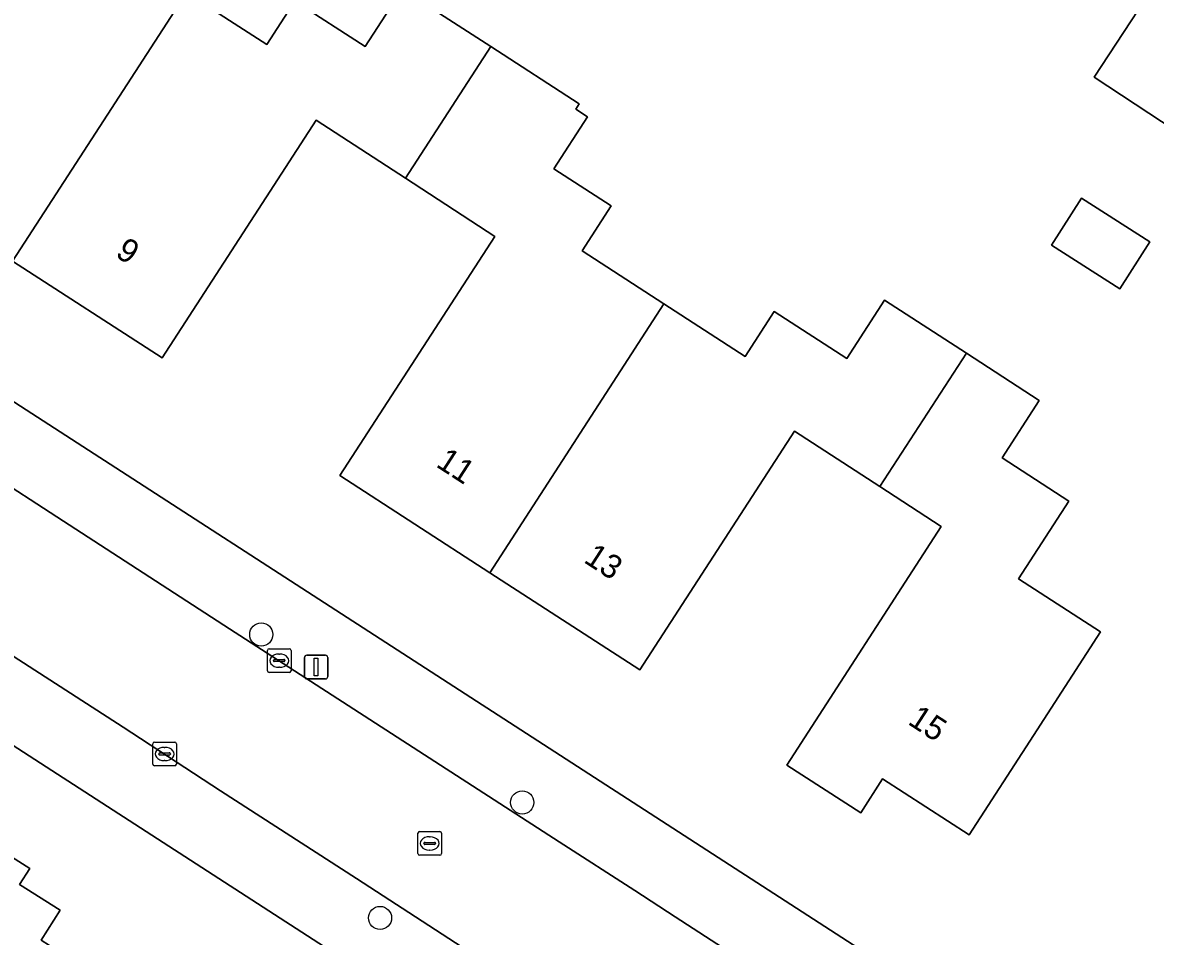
# Model space of a CAD drawing. Extents: x 161139 to 161601, y 381708 to 382245.
# Drawn here: x 161394.2 to 161442.02, y 382009.56 to 382048.13 of the extents above; entities that cross this region are included whole.
import ezdxf

# ---------------------------------------------------------------- set-up
doc = ezdxf.new("R2010")
doc.units = 0
for name, color, linetype in [('IMGEO_Boom', 7, 'Continuous'), ('IMGEO_Erf', 7, 'Continuous'), ('IMGEO_Kolk', 7, 'Continuous'), ('IMGEO_Lichtmast', 7, 'Continuous'), ('IMGEO_Pand', 7, 'Continuous'), ('IMGEO_Pand_nummerreeks', 7, 'Continuous'), ('IMGEO_Rijbaan_lokaal_open', 7, 'Continuous'), ('IMGEO_Rioolput', 7, 'Continuous'), ('IMGEO_Voetpad_open', 7, 'Continuous')]:
    doc.layers.add(name, color=color, linetype=linetype)

msp = doc.modelspace()

# ---------------------------------------------------------------- linework, layer by layer
at = {"layer": 'IMGEO_Boom'}
for centre in [(161404.273, 382022.3), (161415.291, 382015.211), (161409.287, 382010.334)]:
    msp.add_circle(centre, 0.489, dxfattribs=at)
at = {"layer": 'IMGEO_Erf'}
for points in [[(161320.525, 382089.631), (161313.623, 382083.997), (161443.483, 382000), (161462.38, 381987.777), (161470.3, 382000), (161498.24, 382043.117), (161359.011, 382133.266)], [(161421.048, 382000), (161306.066, 382074.349)], [(161401.11, 382049.396), (161404.506, 382047.197), (161405.696, 382049.035), (161408.654, 382047.119), (161410.222, 382049.541), (161413.97, 382047.113), (161417.695, 382044.701), (161417.547, 382044.473), (161418.047, 382044.149), (161416.628, 382041.957), (161419.046, 382040.391), (161417.818, 382038.494), (161421.274, 382036.256), (161424.699, 382034.038), (161425.925, 382035.931), (161428.991, 382033.945), (161430.587, 382036.409), (161434.04, 382034.173), (161437.118, 382032.18), (161435.549, 382029.755), (161438.371, 382027.928), (161436.248, 382024.648), (161439.71, 382022.407), (161436.878, 382018.034), (161434.16, 382013.837), (161430.507, 382016.202), (161429.579, 382014.769), (161426.46, 382016.788), (161432.983, 382026.86), (161430.388, 382028.546), (161426.785, 382030.887), (161420.257, 382020.807), (161413.923, 382024.909), (161407.591, 382029.009), (161414.13, 382039.106), (161410.358, 382041.557), (161406.584, 382044.008), (161400.087, 382033.974), (161393.772, 382038.063)], [(161391.396, 382014.399), (161394.499, 382012.428), (161394.066, 382011.748), (161395.777, 382010.661), (161394.975, 382009.398), (161396.031, 382008.728), (161393.351, 382004.508)]]:
    msp.add_lwpolyline(points, dxfattribs=at)
for points in [[(161442.858, 382051.048), (161448.016, 382047.664), (161444.589, 382042.441), (161439.431, 382045.825)], [(161440.525, 382036.894), (161437.64, 382038.735), (161438.905, 382040.719), (161441.791, 382038.879)]]:
    msp.add_lwpolyline(points, close=True, dxfattribs=at)
at = {"layer": 'IMGEO_Kolk'}
for p, q in [((161404.532, 382020.77), (161404.532, 382021.622)), ((161404.607, 382021.696), (161405.459, 382021.696)), ((161405.533, 382021.622), (161405.533, 382020.77)), ((161404.791, 382021.19), (161404.791, 382021.202)), ((161405.229, 382021.153), (161404.831, 382021.153)), ((161404.834, 382021.239), (161405.232, 382021.239)), ((161405.02, 382021.476), (161405.045, 382021.476)), ((161405.275, 382021.202), (161405.275, 382021.19)), ((161405.459, 382020.696), (161404.607, 382020.696)), ((161405.043, 382020.916), (161405.018, 382020.916)), ((161399.692, 382016.83), (161399.692, 382017.682)), ((161399.767, 382017.756), (161400.619, 382017.756)), ((161400.693, 382017.682), (161400.693, 382016.83)), ((161399.951, 382017.25), (161399.951, 382017.262)), ((161400.389, 382017.213), (161399.991, 382017.213)), ((161399.994, 382017.299), (161400.392, 382017.299)), ((161400.18, 382017.536), (161400.205, 382017.536)), ((161400.435, 382017.262), (161400.435, 382017.25)), ((161400.619, 382016.756), (161399.767, 382016.756)), ((161400.203, 382016.976), (161400.178, 382016.976))]:
    msp.add_line(p, q, dxfattribs=at)
for points in [[(161404.532, 382020.77), (161404.532, 382021.622)], [(161404.607, 382021.696), (161405.459, 382021.696)], [(161405.533, 382021.622), (161405.533, 382020.77)], [(161405.459, 382020.696), (161404.607, 382020.696)], [(161399.692, 382016.83), (161399.692, 382017.682)], [(161399.767, 382017.756), (161400.619, 382017.756)], [(161400.693, 382017.682), (161400.693, 382016.83)], [(161400.619, 382016.756), (161399.767, 382016.756)]]:
    msp.add_lwpolyline(points, dxfattribs=at)
for centre, radius, start, end in [((161404.609, 382021.62), 0.0765, 91.552, 178.448), ((161404.609, 382021.62), 0.0765, 91.552, 178.448), ((161405.457, 382021.62), 0.0765, 1.552, 88.448), ((161405.457, 382021.62), 0.0765, 1.552, 88.448), ((161404.831, 382021.199), 0.0403, 85.8775, 175.7526), ((161404.828, 382021.189), 0.0366, 178.938, 274.7102), ((161405.232, 382021.196), 0.043, 264.8664, 352.4533), ((161405.236, 382021.201), 0.0386, 1.7309, 96.639), ((161404.609, 382020.772), 0.0765, 181.552, 268.448), ((161404.609, 382020.772), 0.0765, 181.552, 268.448), ((161405.457, 382020.772), 0.0765, 271.552, 358.448), ((161405.457, 382020.772), 0.0765, 271.552, 358.448), ((161399.769, 382017.68), 0.0765, 91.552, 178.448), ((161399.769, 382017.68), 0.0765, 91.552, 178.448), ((161400.617, 382017.68), 0.0765, 1.552, 88.448), ((161400.617, 382017.68), 0.0765, 1.552, 88.448), ((161399.991, 382017.259), 0.0403, 85.8775, 175.7526), ((161399.988, 382017.249), 0.0366, 178.938, 274.7102), ((161400.392, 382017.256), 0.043, 264.8664, 352.4533), ((161400.396, 382017.261), 0.0386, 1.7309, 96.639), ((161399.769, 382016.832), 0.0765, 181.552, 268.448), ((161399.769, 382016.832), 0.0765, 181.552, 268.448), ((161400.617, 382016.832), 0.0765, 271.552, 358.448), ((161400.617, 382016.832), 0.0765, 271.552, 358.448)]:
    msp.add_arc(centre, radius, start, end, dxfattribs=at)
for centre, major_axis, ratio, start_param, end_param in [((161405.019, 382021.196), (-0.387, 0.002), 0.722429, 4.712389, 7.853982), ((161405.044, 382021.196), (-0.39, 0.002), 0.717154, 1.570796, 4.712389), ((161400.179, 382017.256), (-0.387, 0.002), 0.722429, 4.712389, 7.853982), ((161400.204, 382017.256), (-0.39, 0.002), 0.717154, 1.570796, 4.712389)]:
    msp.add_ellipse(centre, major_axis=major_axis, ratio=ratio, start_param=start_param, end_param=end_param, dxfattribs=at)
at = {"layer": 'IMGEO_Lichtmast'}
for p, q in [((161406.093, 382020.525), (161406.093, 382021.325)), ((161406.093, 382021.325), (161406.093, 382020.525)), ((161406.193, 382021.425), (161406.983, 382021.425)), ((161406.983, 382021.425), (161406.193, 382021.425)), ((161407.083, 382021.325), (161407.083, 382020.525)), ((161407.083, 382020.525), (161407.083, 382021.325)), ((161406.983, 382020.425), (161406.193, 382020.425)), ((161406.193, 382020.425), (161406.983, 382020.425))]:
    msp.add_line(p, q, dxfattribs=at)
msp.add_lwpolyline([(161406.513, 382021.3), (161406.663, 382021.3), (161406.663, 382020.55), (161406.513, 382020.55), (161406.513, 382021.3)], dxfattribs=at)
for centre, start, end in [((161406.193, 382021.325), 90, 180), ((161406.193, 382021.325), 90, 180), ((161406.983, 382021.325), 0, 90), ((161406.983, 382021.325), 360, 90), ((161406.193, 382020.525), 180, 270), ((161406.193, 382020.525), 180, 270), ((161406.983, 382020.525), 270, 0), ((161406.983, 382020.525), 270, 0)]:
    msp.add_arc(centre, 0.1, start, end, dxfattribs=at)
at = {"layer": 'IMGEO_Pand'}
for points in [[(161393.772, 382038.063), (161401.11, 382049.396), (161397.803, 382051.538), (161399.046, 382053.458), (161396.573, 382055.059), (161397.487, 382056.47), (161396.939, 382056.824), (161397.496, 382057.684), (161393.835, 382060.054), (161390.289, 382054.594), (161393.97, 382052.203), (161387.46, 382042.15)], [(161448.016, 382047.664), (161442.858, 382051.048), (161439.431, 382045.825), (161444.589, 382042.441)], [(161401.11, 382049.396), (161393.772, 382038.063), (161400.087, 382033.974), (161406.584, 382044.008), (161410.358, 382041.557), (161413.97, 382047.113), (161410.222, 382049.541), (161408.654, 382047.119), (161405.696, 382049.035), (161404.506, 382047.197)], [(161413.97, 382047.113), (161410.358, 382041.557), (161414.13, 382039.106), (161407.591, 382029.009), (161413.923, 382024.909), (161421.274, 382036.256), (161417.818, 382038.494), (161419.046, 382040.391), (161416.628, 382041.957), (161418.047, 382044.149), (161417.547, 382044.473), (161417.695, 382044.701)], [(161440.525, 382036.894), (161441.791, 382038.879), (161438.905, 382040.719), (161437.64, 382038.735)], [(161413.923, 382024.909), (161420.257, 382020.807), (161426.785, 382030.887), (161430.388, 382028.546), (161434.04, 382034.173), (161430.587, 382036.409), (161428.991, 382033.945), (161425.925, 382035.931), (161424.699, 382034.038), (161421.274, 382036.256)], [(161430.388, 382028.546), (161432.983, 382026.86), (161426.46, 382016.788), (161429.579, 382014.769), (161430.507, 382016.202), (161434.16, 382013.837), (161436.878, 382018.034), (161439.71, 382022.407), (161436.248, 382024.648), (161438.371, 382027.928), (161435.549, 382029.755), (161437.118, 382032.18), (161434.04, 382034.173)], [(161396.031, 382008.728), (161394.975, 382009.398), (161395.777, 382010.661), (161394.066, 382011.748), (161394.499, 382012.428), (161391.396, 382014.399), (161391.004, 382013.782), (161390.576, 382014.054), (161384.011, 382003.694), (161387.531, 382001.458), (161384.298, 381996.37), (161390.905, 381992.091), (161391.465, 381992.964), (161394.166, 381997.171), (161390.296, 381999.701), (161391.78, 382002.036), (161393.351, 382004.508)]]:
    msp.add_lwpolyline(points, close=True, dxfattribs=at)
at = {"layer": 'IMGEO_Rijbaan_lokaal_open'}
for points in [[(161470.897, 381978.482), (161460.91, 381984.988), (161458.647, 381986.439), (161425.551, 382007.922), (161421.741, 382010.379), (161420.042, 382011.494), (161416.852, 382013.552), (161402.927, 382022.535), (161395.928, 382027.083), (161382.572, 382035.748), (161375.585, 382040.285)], [(161388.068, 382025.069), (161398.439, 382018.395), (161402.555, 382015.697), (161408.287, 382012.005), (161423.318, 382002.239), (161430.314, 381997.713), (161443.856, 381988.93), (161450.889, 381984.377), (161471.977, 381970.646), (161480.897, 381964.849), (161484.169, 381969.847), (161479.648, 381972.672), (161478.162, 381973.768), (161471.247, 381978.26)]]:
    msp.add_lwpolyline(points, dxfattribs=at)
at = {"layer": 'IMGEO_Rioolput'}
for p, q in [((161410.884, 382013.056), (161410.884, 382013.908)), ((161410.959, 382013.982), (161411.811, 382013.982)), ((161411.885, 382013.908), (161411.885, 382013.056)), ((161411.143, 382013.476), (161411.143, 382013.488)), ((161411.581, 382013.439), (161411.183, 382013.439)), ((161411.186, 382013.525), (161411.584, 382013.525)), ((161411.372, 382013.762), (161411.397, 382013.762)), ((161411.627, 382013.488), (161411.627, 382013.476)), ((161411.811, 382012.982), (161410.959, 382012.982)), ((161411.395, 382013.202), (161411.37, 382013.202))]:
    msp.add_line(p, q, dxfattribs=at)
for points in [[(161410.884, 382013.056), (161410.884, 382013.908)], [(161410.959, 382013.982), (161411.811, 382013.982)], [(161411.885, 382013.908), (161411.885, 382013.056)], [(161411.811, 382012.982), (161410.959, 382012.982)]]:
    msp.add_lwpolyline(points, dxfattribs=at)
for centre, radius, start, end in [((161410.961, 382013.906), 0.0765, 91.552, 178.448), ((161410.961, 382013.906), 0.0765, 91.552, 178.448), ((161411.809, 382013.906), 0.0765, 1.552, 88.448), ((161411.809, 382013.906), 0.0765, 1.552, 88.448), ((161411.183, 382013.485), 0.0403, 85.8775, 175.7526), ((161411.18, 382013.475), 0.0366, 178.938, 274.7102), ((161411.584, 382013.482), 0.043, 264.8664, 352.4533), ((161411.588, 382013.487), 0.0386, 1.7309, 96.639), ((161410.961, 382013.058), 0.0765, 181.552, 268.448), ((161410.961, 382013.058), 0.0765, 181.552, 268.448), ((161411.809, 382013.058), 0.0765, 271.552, 358.448), ((161411.809, 382013.058), 0.0765, 271.552, 358.448)]:
    msp.add_arc(centre, radius, start, end, dxfattribs=at)
for centre, major_axis, ratio, start_param, end_param in [((161411.371, 382013.482), (-0.387, 0.002), 0.722429, 4.712389, 7.853982), ((161411.396, 382013.482), (-0.39, 0.002), 0.717154, 1.570796, 4.712389)]:
    msp.add_ellipse(centre, major_axis=major_axis, ratio=ratio, start_param=start_param, end_param=end_param, dxfattribs=at)
at = {"layer": 'IMGEO_Voetpad_open'}
for points in [[(161313.623, 382083.997), (161311.536, 382081.664), (161356.674, 382052.498), (161362.411, 382048.813), (161375.585, 382040.285), (161382.572, 382035.748), (161395.928, 382027.083), (161402.927, 382022.535), (161416.852, 382013.552), (161420.042, 382011.494), (161421.741, 382010.379), (161425.551, 382007.922), (161458.647, 381986.439), (161460.91, 381984.988)], [(161464.955, 381985.959), (161462.38, 381987.777), (161443.483, 382000), (161313.623, 382083.997)], [(161398.439, 382018.395), (161388.068, 382025.069), (161381.679, 382029.228), (161366.307, 382039.161), (161359.944, 382043.32), (161345.442, 382052.667), (161339.032, 382056.795), (161328.504, 382063.628), (161325.321, 382065.668), (161306.338, 382077.878), (161302.036, 382073.583), (161301.893, 382073.339)], [(161306.066, 382074.349), (161421.048, 382000), (161474.804, 381965.241), (161478.068, 381963.057), (161478.909, 381962.515)], [(161481.77, 381964.253), (161480.897, 381964.849), (161471.977, 381970.646), (161450.889, 381984.377), (161443.856, 381988.93), (161430.314, 381997.713), (161423.318, 382002.239), (161408.287, 382012.005), (161402.555, 382015.697), (161398.439, 382018.395)]]:
    msp.add_lwpolyline(points, dxfattribs=at)

# ---------------------------------------------------------------- texts
at = {"layer": 'IMGEO_Pand_nummerreeks'}
for s, rotation, p in [('9', 327.0769, (161398.068, 382038.283)), ('11', 327.0745, (161411.606, 382029.412)), ('13', 327.0745, (161417.843, 382025.373)), ('15', 327.0805, (161431.526, 382018.544))]:
    msp.add_text(s, height=1, rotation=rotation, dxfattribs=at).set_placement(p)

doc.saveas('drawing.dxf')
